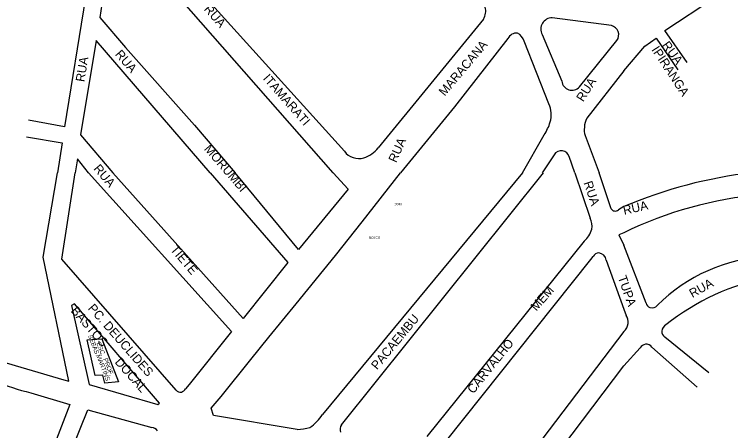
# Model space of a CAD drawing. Extents: x 325709 to 364434, y 7573432 to 7597073.
# Drawn here: x 341270.3 to 341753.5, y 7588827.9 to 7589108.8 of the extents above; entities that cross this region are included whole.
import ezdxf

# ---------------------------------------------------------------- set-up
doc = ezdxf.new("R2010")
doc.units = 0
for name, color, linetype in [('EDIFEXISTENT', 7, 'Continuous'), ('EDIFIDENTIF', 7, 'Continuous'), ('EDIFOBRAEXIS', 7, 'Continuous'), ('LIMITE_BAIRROS_MUNICIPIOS', 7, 'Continuous'), ('LOGRADOURO', 7, 'Continuous'), ('LOGRADOURO_TEXTO', 7, 'Continuous')]:
    doc.layers.add(name, color=color, linetype=linetype)

msp = doc.modelspace()

# ---------------------------------------------------------------- linework, layer by layer
at = {"layer": 'EDIFEXISTENT'}
for p, q in [((341319.49, 7588889.25), (341329.27, 7588889.83)), ((341329.27, 7588889.83), (341340.45, 7588860.91)), ((341324.81, 7588865.25), (341319.49, 7588889.25)), ((341329.92, 7588865.46), (341324.81, 7588865.25)), ((341331.25, 7588860), (341329.92, 7588865.46)), ((341340.45, 7588860.91), (341331.25, 7588860))]:
    msp.add_line(p, q, dxfattribs=at)
at = {"layer": 'EDIFOBRAEXIS'}
for p, q in [((341673.03, 7589101.17), (341633.06, 7589106.44)), ((341626.36, 7589095.26), (341639.58, 7589063.7)), ((341651.54, 7589059.89), (341676.69, 7589091.22))]:
    msp.add_line(p, q, dxfattribs=at)
for centre, radius, start, end in [((341633.01, 7589098.87), 7.57, 89.5846, 208.5573), ((341671.75, 7589095.05), 6.25, 322.1933, 78.1994), ((341646.39, 7589064.41), 6.85, 185.94, 318.7253)]:
    msp.add_arc(centre, radius, start, end, dxfattribs=at)
at = {"layer": 'LOGRADOURO'}
for p, q in [((341356.01, 7589353.22), (341304.02, 7589032.97)), ((341336.85, 7589162.7), (341327.87, 7589106.6)), ((341485.23, 7589001.91), (341343.57, 7589163.59)), ((341709.18, 7589097.81), (341803.5, 7589161.17)), ((341492.91, 7589016.39), (341388.89, 7589131.76)), ((341586.66, 7589105.61), (341515.69, 7589018.72)), ((341724.11, 7589076.26), (341709.18, 7589097.81)), ((341703.35, 7589092.69), (341717.92, 7589071.41)), ((341325.47, 7589091.1), (341314.97, 7589027.44)), ((341402.34, 7589001.91), (341325.47, 7589091.1)), ((341630.93, 7589048.43), (341614.19, 7589090.67)), ((341681.39, 7589070.62), (341656.5, 7589038.65)), ((341304.02, 7589032.97), (341279.84, 7589037.48)), ((341278.47, 7589026.19), (341302.6, 7589022.14)), ((341314.97, 7589027.44), (341336.62, 7589001.91)), ((341613.11, 7589001.91), (341627.69, 7589027.44)), ((341655.33, 7589027.08), (341664.87, 7589001.91)), ((341302.6, 7589022.14), (341299.38, 7589001.91)), ((341312.88, 7589011.43), (341311.22, 7589001.91)), ((341320.32, 7589001.91), (341312.88, 7589011.43)), ((341634.35, 7589014.07), (341626.23, 7589001.91)), ((341648.39, 7589001.91), (341644.57, 7589012.79)), ((341302.22, 7588943.64), (341311.22, 7589001.91)), ((341320.32, 7589001.91), (341416.73, 7588894.9)), ((341424.64, 7588903.71), (341336.62, 7589001.91)), ((341402.34, 7589001.91), (341454.7, 7588941.32)), ((341462.05, 7588950.23), (341419.28, 7589001.91)), ((341613.11, 7589001.91), (341478.21, 7588838.88)), ((341485.23, 7589001.91), (341495.55, 7588990.78)), ((341490.9, 7588831.83), (341627.17, 7589001.91)), ((341648.39, 7589001.91), (341658.76, 7588971.27)), ((341672.98, 7588977.6), (341664.87, 7589001.91)), ((341495.55, 7588990.78), (341462.05, 7588950.23)), ((341681.39, 7588979.07), (341677.82, 7588976.89)), ((341681.39, 7588961.42), (341678.14, 7588960.01)), ((341678.14, 7588960.01), (341681.39, 7588952.99)), ((341654.72, 7588955.76), (341548.57, 7588823.89)), ((341696.39, 7588914), (341681.39, 7588952.99)), ((341379.34, 7588855.33), (341302.22, 7588943.64)), ((341669.62, 7588943.03), (341681.39, 7588909.88)), ((341454.7, 7588941.32), (341424.64, 7588903.71)), ((341368.18, 7588846.54), (341310.92, 7588913.47)), ((341681.39, 7588909.88), (341683.09, 7588905.63)), ((341681.39, 7588894.87), (341621.3, 7588815.62)), ((341738.86, 7588866.97), (341709.16, 7588891.11)), ((341681.39, 7588871.74), (341692.52, 7588883.88)), ((341700.42, 7588884.26), (341730.79, 7588857.28)), ((341626.15, 7588798.61), (341681.39, 7588871.74)), ((341281.3, 7588853.45), (341307.71, 7588845.63)), ((341307.71, 7588845.63), (341255.2, 7588710.64)), ((341264.91, 7588704.5), (341319.75, 7588841.95)), ((341319.75, 7588841.95), (341362.91, 7588830.17))]:
    msp.add_line(p, q, dxfattribs=at)
for points in [[(341327.87, 7589106.6), (341345.29, 7589086.47), (341391.84, 7589034.09), (341419.28, 7589001.91)], [(341603.23, 7589092.55), (341567.22, 7589046.43), (341530.87, 7589001.91)], [(341681.39, 7589070.62), (341695.64, 7589087.34), (341703.35, 7589092.69)], [(341307.06, 7588861.27), (341289.81, 7588945.06), (341299.38, 7589001.91)], [(341403.1, 7588843.13), (341409.69, 7588851.06), (341429.81, 7588875.94), (341441.93, 7588890.97), (341460.4, 7588913.57), (341486.95, 7588946.18), (341504.93, 7588968.81), (341530.87, 7589001.91)], [(341561.19, 7588820.45), (341659.06, 7588943.42), (341660.66, 7588945.45)], [(341310.92, 7588913.47), (341308.88, 7588912.31), (341320.82, 7588859.07)], [(341416.73, 7588894.9), (341388.13, 7588859.13), (341385.8, 7588856.12)], [(341256.97, 7588875.85), (341303.56, 7588862.29), (341307.06, 7588861.27)], [(341320.82, 7588859.07), (341366.98, 7588845.49), (341368.18, 7588846.54)], [(341461.14, 7588828.78), (341404.72, 7588838.11), (341403.1, 7588843.13)]]:
    msp.add_lwpolyline(points, dxfattribs=at)
for centre, radius, start, end in [((341579, 7589110.87), 9.3, 325.5785, 17.2864), ((341608.95, 7589089.75), 6.37, 83.2138, 153.9346), ((341605.61, 7589088.12), 8.95, 16.579, 62.7842), ((341612.87, 7589041.04), 19.51, 345.5856, 22.2525), ((341597.53, 7589046.81), 35.85, 327.3016, 342.7575), ((341666.75, 7589032.51), 11.95, 149.0826, 179.6467), ((341665.74, 7589030.86), 11.07, 171.0636, 199.9615), ((341502.8, 7589024.06), 12.52, 217.8033, 284.7556), ((341500.26, 7589030.53), 19.43, 287.1339, 322.579), ((341639.18, 7589011.14), 5.65, 80.5699, 148.7912), ((341639.5, 7589011.52), 5.22, 13.9818, 83.3697), ((341802.67, 7588694.79), 309.07, 96.4431, 113.1044), ((341797.19, 7588723.89), 264.25, 95.0263, 115.9898), ((341675.44, 7588978.85), 2.76, 206.8299, 257.8191), ((341675.45, 7588980.08), 3.97, 261.5355, 306.7015), ((341648.44, 7588965.84), 11.65, 350.0887, 27.7832), ((341640.77, 7588970.47), 20.27, 313.4714, 340.8819), ((341665.03, 7588942.76), 5.13, 94.2311, 148.3804), ((341663.59, 7588941.82), 6.15, 11.3686, 80.058), ((341785.45, 7588830.42), 115.59, 93.6339, 134.7135), ((341812, 7588770.11), 164.73, 101.4385, 128.3359), ((341700.62, 7588915.17), 4.38, 195.4008, 249.3159), ((341700.56, 7588915.3), 4.49, 250.601, 322.3788), ((341677.21, 7588901.5), 7.18, 350.248, 35.0663), ((341676.57, 7588900.93), 7.75, 308.528, 355.2293), ((341712.12, 7588894.9), 4.98, 117.5129, 177.065), ((341711.09, 7588894.59), 3.98, 171.8466, 241.0076), ((341697.22, 7588880.84), 5.59, 102.7353, 147.1138), ((341696.51, 7588881.57), 4.75, 34.4826, 96.2995), ((341333.58, 7589058.35), 211.47, 241.8638, 255.6877), ((341378.88, 7588861.96), 9.05, 296.8982, 319.8177), ((341382.4, 7588857.73), 3.88, 218.121, 278.6498), ((341455.02, 7588853.17), 27.23, 302.2601, 328.3543), ((341496.84, 7588828.63), 6.75, 151.71, 195.257), ((341362.54, 7588824.87), 5.3, 35.1921, 85.9762), ((341461.3, 7588854.42), 25.65, 269.6437, 288.7791)]:
    msp.add_arc(centre, radius, start, end, dxfattribs=at)

# ---------------------------------------------------------------- texts
at = {"layer": 'EDIFIDENTIF'}
for s, p in [('SEBAS.', (341319.92, 7588892.02)), ('ESC.', (341325.66, 7588886.94)), ('MARTINS', (341325.42, 7588878.62)), ('PROF.', (341330.17, 7588876.24))]:
    msp.add_text(s, height=3, rotation=291.1353, dxfattribs=at).set_placement(p)
at = {"layer": 'LIMITE_BAIRROS_MUNICIPIOS'}
for s, p in [('DOM', (341526.57, 7588980.05)), ('BOSCO', (341509.63, 7588957.47))]:
    msp.add_text(s, height=1.5, dxfattribs=at).set_placement(p)
at = {"layer": 'LOGRADOURO_TEXTO'}
for s, rotation, p in [('RUA', 311.2243, (341397.79, 7589112.03)), ('MARACANA', 49.9265, (341560.58, 7589053.28)), ('IPIRANGA', 303.4288, (341699.82, 7589084.91)), ('RUA', 306.1573, (341706.88, 7589087.93)), ('RUA', 310.757, (341337.89, 7589081.65)), ('RUA', 80.7785, (341317.47, 7589062.93)), ('ITAMARATI', 311.2243, (341437.63, 7589065.31)), ('RUA', 57.3157, (341653.98, 7589049.36)), ('MORUMBI', 310.757, (341397.94, 7589017.8)), ('RUA', 66.0227, (341527.82, 7589008.34)), ('RUA', 310.3024, (341323.36, 7589004.5)), ('RUA', 288.6954, (341654.19, 7588995.18)), ('RUA', 12.8109, (341681.66, 7588973.54)), ('TIETE', 310.3024, (341375.15, 7588949.93)), ('TUPA', 289.5542, (341677.28, 7588931.37)), ('RUA ', 29.2907, (341727.66, 7588917.36)), ('MEM', 48.8337, (341622.44, 7588908.21)), ('PC.', 311.1303, (341319.59, 7588910.24)), ('BASTOS', 311.1303, (341308.03, 7588908.52)), ('PACAEMBU', 50.3923, (341515.01, 7588868.6)), ('DEUCLIDES', 311.1303, (341329.89, 7588898.51)), ('CARVALHO', 51.1672, (341579.9, 7588852.42)), ('DOCAL', 311.3284, (341337.69, 7588873.96))]:
    msp.add_text(s, height=6, rotation=rotation, dxfattribs=at).set_placement(p)

doc.saveas('drawing.dxf')
